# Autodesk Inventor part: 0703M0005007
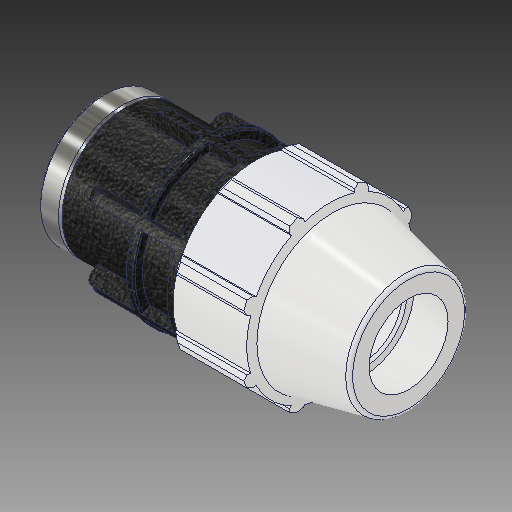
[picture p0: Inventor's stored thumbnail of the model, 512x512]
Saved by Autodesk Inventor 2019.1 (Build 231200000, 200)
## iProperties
Created: 2017-02
Part Number: 0703M0005007
Material: PVC-Piping
Description: PLASSON FEMALE ADAPTOR 1/2'' - 3/4''F
Document SubType Name: Modeling
Designer: KIM
Mass: 92.6774 g
Surface Area: 199.44 cm^2
Volume: 66.1981 cm^3
Density: 1.4 g/cm^3
Appearance: PTFE
Author: KIM
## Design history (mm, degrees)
derived "0703M0.ipt"
feature "Solid1::0703M0.ipt"
tag "TaggingFeature1"
body "Solid1"
other parameters: "d2" = 21.2, "d4" = 11.72029, "d5" = 20.5105, "d7" = 48.006, "d9" = 11.72029, "d11" = 2.34406, "d12" = 38.4048, "d13" = 120 deg, "d14" = 31.8, "d15" = 12 deg, "d16" = 43.2054, "d18" = 1.06, "d19" = 35 deg, "d20" = 17.5 deg, "d21" = 44.64558, "d23" = 0, "d25" = 360 deg, "d27" = 0.96012, "d34" = 2.4003, "d35" = 24.6126, "d36" = 0, "d42" = 20.5105, "d43" = 1.44018, "d46" = 0.636, "d49" = 58.928, "d51" = 82.042, "d53" = 0.424, "d55" = 360 deg, "d61" = 19.05, "d62" = 16.96, "d63" = 24.117, "d64" = 27.34733, "d65" = 2.4003, "d66" = 0.5, "d67" = 1, "d68" = 5.715, "d69" = 34.56432, "d70" = 1.20015, "d_" = 21.2, "E_" = 48.006, "H_" = 82.042, "l_" = 58.928, "l_2" = 19.05, "Rp_" = 24.117
